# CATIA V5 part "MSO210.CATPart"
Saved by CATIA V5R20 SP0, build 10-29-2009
Part number: MSO210
Definition: NONE
Nomenclature: MSO210
Source: Unknown
Description: MSO210
Bounding box of the stored display mesh (mm): x 0 to 12, y -5 to 5, z -5 to 5
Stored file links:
  C:\Users\Utente\Desktop\IO LAVORO\3D X SITO CF\X SITO\PLASTICA\CFMR\MSO210.CATPart
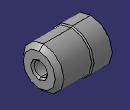
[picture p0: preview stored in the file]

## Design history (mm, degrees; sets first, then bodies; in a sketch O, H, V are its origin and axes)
Body1 "MSO210" (main body)
  Solid1: solid without history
